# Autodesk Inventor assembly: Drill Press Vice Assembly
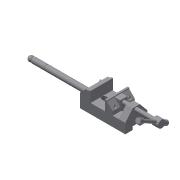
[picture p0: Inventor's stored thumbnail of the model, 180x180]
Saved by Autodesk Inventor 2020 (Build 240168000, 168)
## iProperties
Created: 2011-07
Part Number: Drill Press Vice Assembly
Document SubType Name: Assembly
Designer: CadCim
Author: CadCim
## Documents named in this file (9)
- D:\Autodesk Inventor_2020\Resources\Resources\Inventor_2019_tut\Inventor_2019_tut\c13_Inv_2019_tut\c13_Inv_tut_2019\c13-tut02-inv\Drill Press vice\Drill Press Vice\Drill Press Vice Assembly.iam
- D:\Autodesk Inventor_2020\Resources\Resources\Inventor_2019_tut\Inventor_2019_tut\c13_Inv_2019_tut\c13_Inv_tut_2019\c13-tut02-inv\Drill Press vice\Drill Press Vice\Base.ipt
- D:\Autodesk Inventor_2020\Resources\Resources\Inventor_2019_tut\Inventor_2019_tut\c13_Inv_2019_tut\c13_Inv_tut_2019\c13-tut02-inv\Drill Press vice\Drill Press Vice\Jaw Face.ipt
- D:\Autodesk Inventor_2020\Resources\Resources\Inventor_2019_tut\Inventor_2019_tut\c13_Inv_2019_tut\c13_Inv_tut_2019\c13-tut02-inv\Drill Press vice\Drill Press Vice\Movable Jaw.ipt
- D:\Autodesk Inventor_2020\Resources\Resources\Inventor_2019_tut\Inventor_2019_tut\c13_Inv_2019_tut\c13_Inv_tut_2019\c13-tut02-inv\Drill Press vice\Drill Press Vice\Safety Handle.ipt
- D:\Autodesk Inventor_2020\Resources\Resources\Inventor_2019_tut\Inventor_2019_tut\c13_Inv_2019_tut\c13_Inv_tut_2019\c13-tut02-inv\Drill Press vice\Drill Press Vice\Clamp Screw.ipt
- D:\Autodesk Inventor_2020\Resources\Resources\Inventor_2019_tut\Inventor_2019_tut\c13_Inv_2019_tut\c13_Inv_tut_2019\c13-tut02-inv\Drill Press vice\Drill Press Vice\Clamp Screw Handle.ipt
- D:\Autodesk Inventor_2020\Resources\Resources\Inventor_2019_tut\Inventor_2019_tut\c13_Inv_2019_tut\c13_Inv_tut_2019\c13-tut02-inv\Drill Press vice\Drill Press Vice\Handle Stop.ipt
- D:\Autodesk Inventor_2020\Resources\Resources\Inventor_2019_tut\Inventor_2019_tut\c13_Inv_2019_tut\c13_Inv_tut_2019\c13-tut02-inv\Drill Press vice\Drill Press Vice\Cap Screw.ipt
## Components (13 placed, 8 different names)
1. Base:1 — Insert:3, Insert:9, Insert:10, Mate:8, Mate:9, Mate:12, Mate:13
2. Jaw Face:1 — Mate:10, Mate:11, Mate:12
3. Movable Jaw:1 — Mate:3, Insert:4, Insert:11, Insert:12, Mate:9, Mate:13, Mate:15
4. Safety Handle:1 — Insert:3
5. Clamp Screw:1 — Mate:3, Insert:4, Mate:4, Mate:6, Mate:8
6. Clamp Screw Handle:1 — Mate:4, Insert:7, Insert:8
7. Jaw Face:2 — Mate:14, Mate:15
8. Handle Stop:1 — Insert:7, Mate:6
9. Handle Stop:2 — Insert:8
10. Cap Screw:1 — Insert:12
11. Cap Screw:2 — Insert:11, Mate:14
12. Cap Screw:3 — Insert:10, Mate:11
13. Cap Screw:4 — Insert:9, Mate:10
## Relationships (19: Mate 11, Insert 8)
- Insert:3: Base:1 ↔ Safety Handle:1
- Mate:3: Movable Jaw:1 ↔ Clamp Screw:1
- Insert:4: Movable Jaw:1 ↔ Clamp Screw:1
- Mate:4: Clamp Screw:1 ↔ Clamp Screw Handle:1
- Insert:7: Clamp Screw Handle:1 ↔ Handle Stop:1
- Insert:8: Clamp Screw Handle:1 ↔ Handle Stop:2
- Mate:6: Clamp Screw:1 ↔ Handle Stop:1
- Insert:9: Base:1 ↔ Cap Screw:4
- Insert:10: Base:1 ↔ Cap Screw:3
- Insert:11: Movable Jaw:1 ↔ Cap Screw:2
- Insert:12: Movable Jaw:1 ↔ Cap Screw:1
- Mate:8: Base:1 ↔ Clamp Screw:1
- Mate:9: Base:1 ↔ Movable Jaw:1
- Mate:10: Jaw Face:1 ↔ Cap Screw:4
- Mate:11: Jaw Face:1 ↔ Cap Screw:3
- Mate:12: Base:1 ↔ Jaw Face:1
- Mate:13: Base:1 ↔ Movable Jaw:1
- Mate:14: Jaw Face:2 ↔ Cap Screw:2
- Mate:15: Movable Jaw:1 ↔ Jaw Face:2
